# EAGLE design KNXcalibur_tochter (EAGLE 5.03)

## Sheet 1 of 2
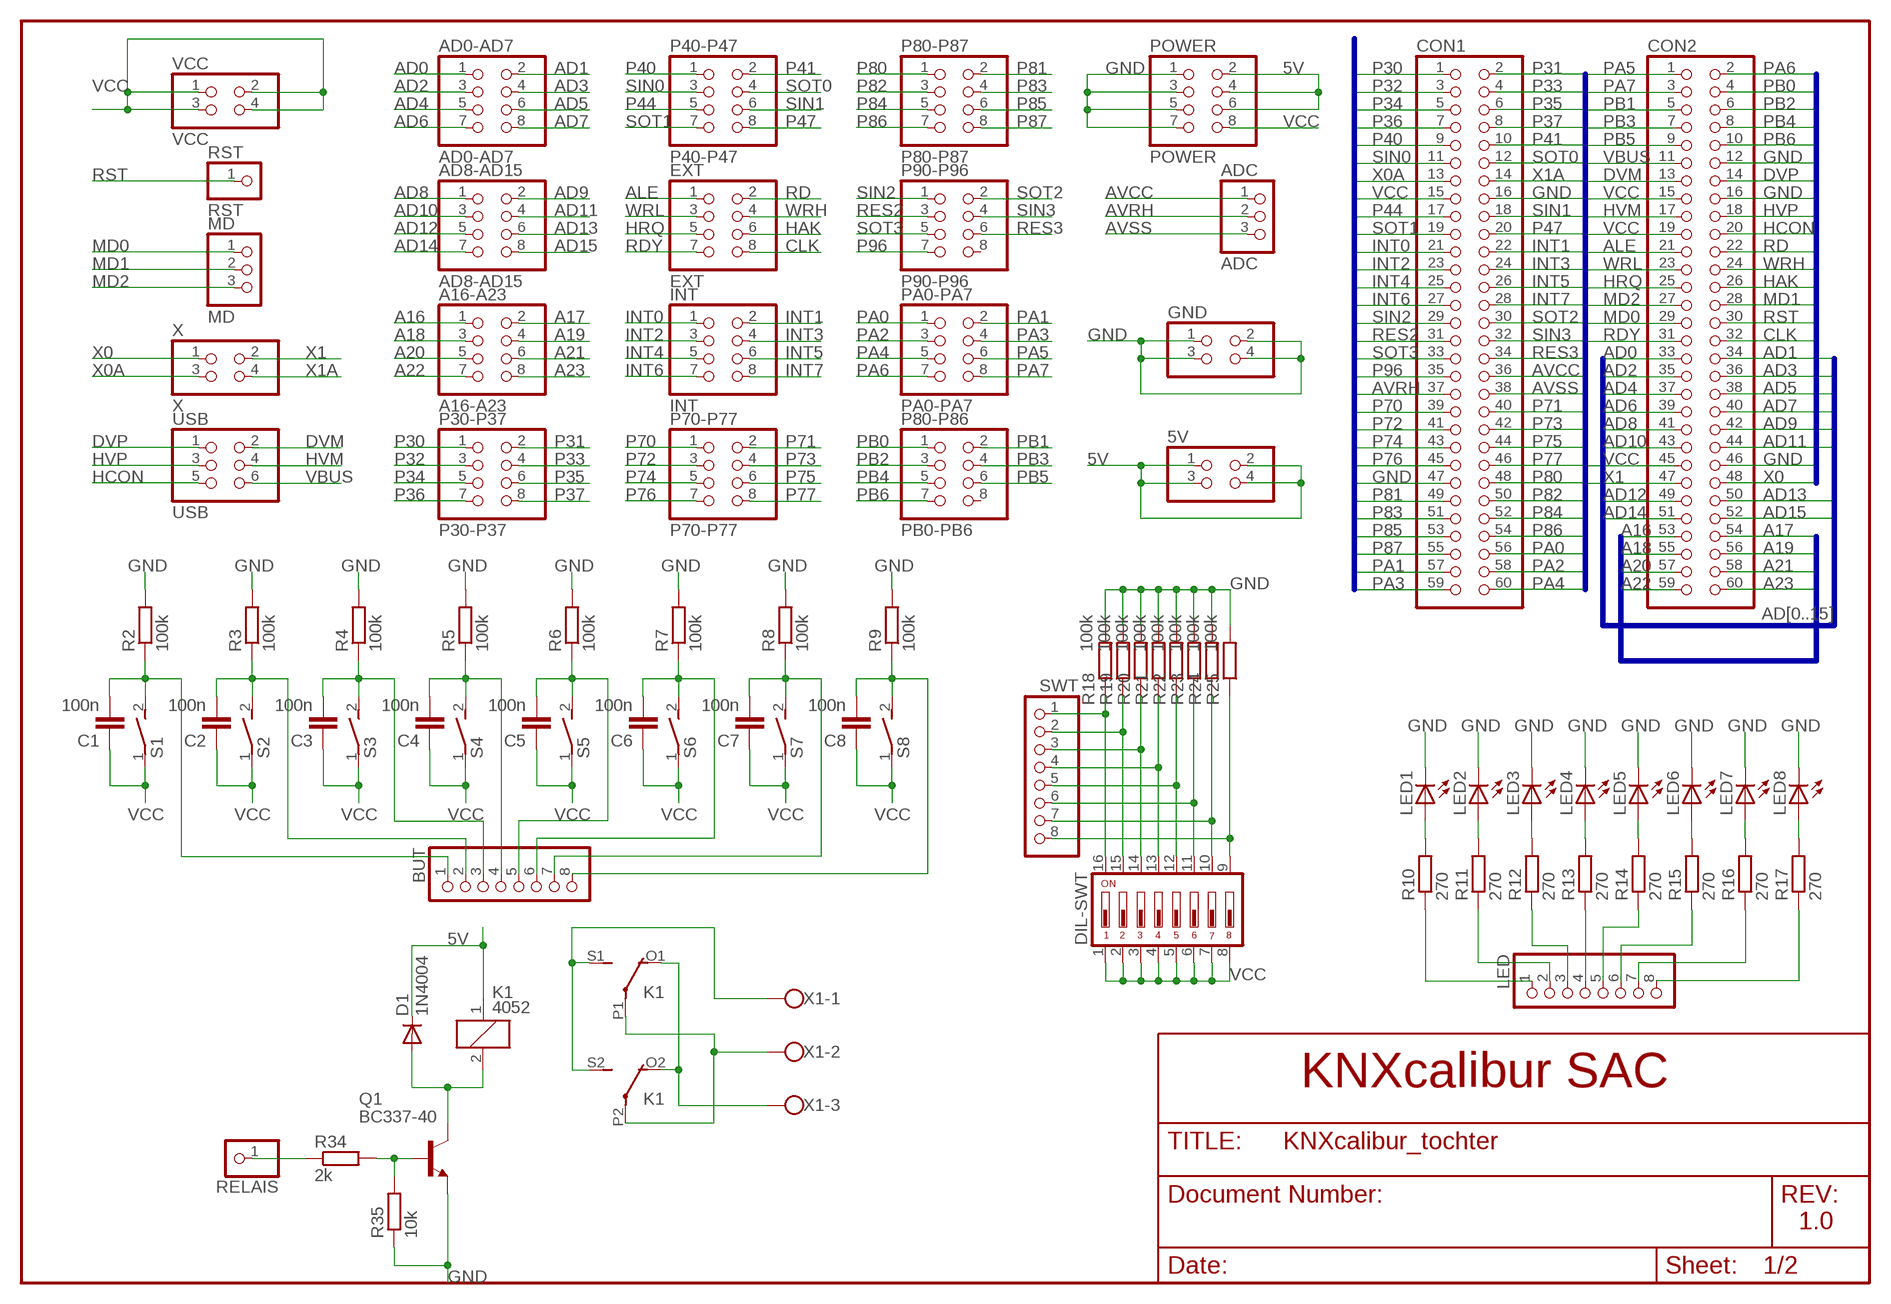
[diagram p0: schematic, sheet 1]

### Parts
5V  PINHD-2X2  [2X02]
A16-A23  A16-A23  PINHD-2X4  [2X04]
AD0-AD7  AD0-AD7  PINHD-2X4  [2X04]
AD8-AD15  AD8-AD15  PINHD-2X4  [2X04]
ADC  ADC  PINHD-1X3  [1X03]
BUT  PINHD-1X8  [1X08]
C1  100n  C-EUC0805  [C0805]
C2  100n  C-EUC0805  [C0805]
C3  100n  C-EUC0805  [C0805]
C4  100n  C-EUC0805  [C0805]
C5  100n  C-EUC0805  [C0805]
C6  100n  C-EUC0805  [C0805]
C7  100n  C-EUC0805  [C0805]
C8  100n  C-EUC0805  [C0805]
CON1  PINHD-2X30  [2X30]
CON2  PINHD-2X30  [2X30]
D1  1N4004  [DO41-10]
DIL-SWT  DIP08YL  [DIP08YL]
EXT  EXT  PINHD-2X4  [2X04]
GND  PINHD-2X2  [2X02]
INT  INT  PINHD-2X4  [2X04]
K1  4052  [F4052]
LED  PINHD-1X8  [1X08]
LED1  LED3MM  [LED3MM]
LED2  LED3MM  [LED3MM]
LED3  LED3MM  [LED3MM]
LED4  LED3MM  [LED3MM]
LED5  LED3MM  [LED3MM]
LED6  LED3MM  [LED3MM]
LED7  LED3MM  [LED3MM]
LED8  LED3MM  [LED3MM]
MD  MD  PINHD-1X3  [1X03]
P30-P37  P30-P37  PINHD-2X4  [2X04]
P40-P47  P40-P47  PINHD-2X4  [2X04]
P70-P77  P70-P77  PINHD-2X4  [2X04]
P80-P86  PB0-PB6  PINHD-2X4  [2X04]
P80-P87  P80-P87  PINHD-2X4  [2X04]
P90-P96  P90-P96  PINHD-2X4  [2X04]
PA0-PA7  PA0-PA7  PINHD-2X4  [2X04]
POWER  POWER  PINHD-2X4  [2X04]
Q1  BC337-40  [TO92]
R2  100k  R-EU_R0805  [R0805]
R3  100k  R-EU_R0805  [R0805]
R4  100k  R-EU_R0805  [R0805]
R5  100k  R-EU_R0805  [R0805]
R6  100k  R-EU_R0805  [R0805]
R7  100k  R-EU_R0805  [R0805]
R8  100k  R-EU_R0805  [R0805]
R9  100k  R-EU_R0805  [R0805]
R10  270  R-EU_R0805  [R0805]
R11  270  R-EU_R0805  [R0805]
R12  270  R-EU_R0805  [R0805]
R13  270  R-EU_R0805  [R0805]
R14  270  R-EU_R0805  [R0805]
R15  270  R-EU_R0805  [R0805]
R16  270  R-EU_R0805  [R0805]
R17  270  R-EU_R0805  [R0805]
R18  100k  R-EU_R0805  [R0805]
R19  100k  R-EU_R0805  [R0805]
R20  100k  R-EU_R0805  [R0805]
R21  100k  R-EU_R0805  [R0805]
R22  100k  R-EU_R0805  [R0805]
R23  100k  R-EU_R0805  [R0805]
R24  100k  R-EU_R0805  [R0805]
R25  100k  R-EU_R0805  [R0805]
R34  2k  R-EU_R0805  [R0805]
R35  10k  R-EU_R0805  [R0805]
RELAIS  PINHD-1X1  [1X01]
RST  RST  PINHD-1X1  [1X01]
S1  DTS-3  [DTS-3]
S2  DTS-3  [DTS-3]
S3  DTS-3  [DTS-3]
S4  DTS-3  [DTS-3]
S5  DTS-3  [DTS-3]
S6  DTS-3  [DTS-3]
S7  DTS-3  [DTS-3]
S8  DTS-3  [DTS-3]
SWT  PINHD-1X8  [1X08]
USB  USB  PINHD-2X3  [2X03]
VCC  VCC  PINHD-2X2  [2X02]
X  X  PINHD-2X2  [2X02]
X1  W237-103  [W237-103]

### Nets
5V: 5V.1 5V.2 5V.3 5V.4 D1.C K1.1 POWER.2 POWER.4 POWER.6 ; also sheet 2
A16: A16-A23.1 CON2.53
A17: A16-A23.2 CON2.54
A18: A16-A23.3 CON2.55
A19: A16-A23.4 CON2.56
A20: A16-A23.5 CON2.57
A21: A16-A23.6 CON2.58
A22: A16-A23.7 CON2.59
A23: A16-A23.8 CON2.60
AD0: AD0-AD7.1 CON2.33
AD1: AD0-AD7.2 CON2.34
AD2: AD0-AD7.3 CON2.35
AD3: AD0-AD7.4 CON2.36
AD4: AD0-AD7.5 CON2.37
AD5: AD0-AD7.6 CON2.38
AD6: AD0-AD7.7 CON2.39
AD7: AD0-AD7.8 CON2.40
AD8: AD8-AD15.1 CON2.41
AD9: AD8-AD15.2 CON2.42
AD10: AD8-AD15.3 CON2.43
AD11: AD8-AD15.4 CON2.44
AD12: AD8-AD15.5 CON2.49
AD13: AD8-AD15.6 CON2.50
AD14: AD8-AD15.7 CON2.51
AD15: AD8-AD15.8 CON2.52
ALE: CON2.21 EXT.1
AVCC: ADC.1 CON1.36
AVRH: ADC.2 CON1.37
AVSS: ADC.3 CON1.38
CLK: CON2.32 EXT.8
DVM: CON2.13 USB.2
DVP: CON2.14 USB.1
GND: CON1.16 CON1.47 CON2.12 CON2.16 CON2.46 GND.1 GND.2 GND.3 GND.4 LED1.K(C) LED2.K(C) LED3.K(C) LED4.K(C) LED5.K(C) LED6.K(C) LED7.K(C) LED8.K(C) POWER.1 POWER.3 POWER.5 POWER.7 Q1.1(E) R2.2 R3.2 R4.2 R5.2 R6.2 R7.2 R8.2 R9.2 R18.2 R19.2 R20.2 R21.2 R22.2 R23.2 R24.2 R25.2 R35.1 ; also sheet 2
HAK: CON2.26 EXT.6
HCON: CON2.20 USB.5
HRQ: CON2.25 EXT.5
HVM: CON2.17 USB.4
HVP: CON2.18 USB.3
INT0: CON1.21 INT.1
INT1: CON1.22 INT.2
INT2: CON1.23 INT.3 ; also sheet 2
INT3: CON1.24 INT.4 ; also sheet 2
INT4: CON1.25 INT.5 ; also sheet 2
INT5: CON1.26 INT.6 ; also sheet 2
INT6: CON1.27 INT.7 ; also sheet 2
INT7: CON1.28 INT.8
MD0: CON2.29 MD.1
MD1: CON2.28 MD.2
MD2: CON2.27 MD.3
N$2: DIL-SWT.16 R18.1 SWT.1
N$3: DIL-SWT.15 R19.1 SWT.2
N$4: DIL-SWT.14 R20.1 SWT.3
N$5: DIL-SWT.13 R21.1 SWT.4
N$6: DIL-SWT.12 R22.1 SWT.5
N$7: DIL-SWT.11 R23.1 SWT.6
N$8: DIL-SWT.10 R24.1 SWT.7
N$9: DIL-SWT.9 R25.1 SWT.8
N$15: BUT.1 C1.2 R2.1 S1.2
N$16: BUT.2 C2.2 R3.1 S2.2
N$17: BUT.3 C3.2 R4.1 S3.2
N$18: BUT.4 C4.2 R5.1 S4.2
N$19: BUT.5 C5.2 R6.1 S5.2
N$20: BUT.6 C6.2 R7.1 S6.2
N$21: BUT.7 C7.2 R8.1 S7.2
N$22: BUT.8 C8.2 R9.1 S8.2
N$23: LED1.A R10.2
N$24: LED.1 R10.1
N$25: LED2.A R11.2
N$26: LED.2 R11.1
N$27: LED3.A R12.2
N$28: LED.3 R12.1
N$29: LED4.A R13.2
N$30: LED.4 R13.1
N$31: LED5.A R14.2
N$32: LED.5 R14.1
N$33: LED6.A R15.2
N$34: LED.6 R15.1
N$35: LED7.A R16.2
N$36: LED.7 R16.1
N$37: LED8.A R17.2
N$38: LED.8 R17.1
N$54: K1.P1(2:P) K1.P2(3:P) X1.2
N$55: R34.1 RELAIS.1
N$57: K1.S1(2:S) K1.S2(3:S) X1.1
N$58: K1.O1(2:O) K1.O2(3:O) X1.3
N$59: Q1.2(B) R34.2 R35.2
N$61: D1.A K1.2 Q1.3(C)
P30: CON1.1 P30-P37.1 ; also sheet 2
P31: CON1.2 P30-P37.2 ; also sheet 2
P32: CON1.3 P30-P37.3 ; also sheet 2
P33: CON1.4 P30-P37.4 ; also sheet 2
P34: CON1.5 P30-P37.5 ; also sheet 2
P35: CON1.6 P30-P37.6
P36: CON1.7 P30-P37.7
P37: CON1.8 P30-P37.8
P40: CON1.9 P40-P47.1
P41: CON1.10 P40-P47.2
P44: CON1.17 P40-P47.5
P47: CON1.20 P40-P47.8
P70: CON1.39 P70-P77.1
P71: CON1.40 P70-P77.2
P72: CON1.41 P70-P77.3
P73: CON1.42 P70-P77.4
P74: CON1.43 P70-P77.5
P75: CON1.44 P70-P77.6
P76: CON1.45 P70-P77.7
P77: CON1.46 P70-P77.8
P80: CON1.48 P80-P87.1
P81: CON1.49 P80-P87.2
P82: CON1.50 P80-P87.3
P83: CON1.51 P80-P87.4
P84: CON1.52 P80-P87.5
P85: CON1.53 P80-P87.6
P86: CON1.54 P80-P87.7
P87: CON1.55 P80-P87.8
P96: CON1.35 P90-P96.7
PA0: CON1.56 PA0-PA7.1
PA1: CON1.57 PA0-PA7.2
PA2: CON1.58 PA0-PA7.3
PA3: CON1.59 PA0-PA7.4
PA4: CON1.60 PA0-PA7.5
PA5: CON2.1 PA0-PA7.6
PA6: CON2.2 PA0-PA7.7
PA7: CON2.3 PA0-PA7.8
PB0: CON2.4 P80-P86.1
PB1: CON2.5 P80-P86.2
PB2: CON2.6 P80-P86.3
PB3: CON2.7 P80-P86.4
PB4: CON2.8 P80-P86.5
PB5: CON2.9 P80-P86.6
PB6: CON2.10 P80-P86.7
RD: CON2.22 EXT.2
RDY: CON2.31 EXT.7
RES2: CON1.31 P90-P96.3
RES3: CON1.34 P90-P96.6
RST: CON2.30 RST.1
SIN0: CON1.11 P40-P47.3
SIN1: CON1.18 P40-P47.6
SIN2: CON1.29 P90-P96.1
SIN3: CON1.32 P90-P96.4
SOT0: CON1.12 P40-P47.4
SOT1: CON1.19 P40-P47.7
SOT2: CON1.30 P90-P96.2
SOT3: CON1.33 P90-P96.5
VBUS: CON2.11 USB.6
VCC: C1.1 C2.1 C3.1 C4.1 C5.1 C6.1 C7.1 C8.1 CON1.15 CON2.15 CON2.19 CON2.45 DIL-SWT.1 DIL-SWT.2 DIL-SWT.3 DIL-SWT.4 DIL-SWT.5 DIL-SWT.6 DIL-SWT.7 DIL-SWT.8 POWER.8 S1.1 S2.1 S3.1 S4.1 S5.1 S6.1 S7.1 S8.1 VCC.1 VCC.2 VCC.3 VCC.4 ; also sheet 2
WRH: CON2.24 EXT.4
WRL: CON2.23 EXT.3
X0: CON2.48 X.1
X0A: CON1.13 X.3
X1: CON2.47 X.2
X1A: CON1.14 X.4
Unconnected: P80-P86.8 P90-P96.8

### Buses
AD[0..15]
A[0..23]
P[30..37],P40,P41,P44,P47,SIN[0..3],SOT[0..3],INT[0..7],X0A,X1A,VCC,GND,RES2,RES3,P96,AVCC,AVRH,AVSS,P[70..77],P[80..87],PA[0..7],PB[0..6],VBUS,DVM,DVP,HVM,HVP,HCON,ALE,RD,WRL,WRH,HRQ,HAK,RDY,CLK,MD[0..2],RST,X[0..1]

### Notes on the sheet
- KNXcalibur SAC
- 1.0

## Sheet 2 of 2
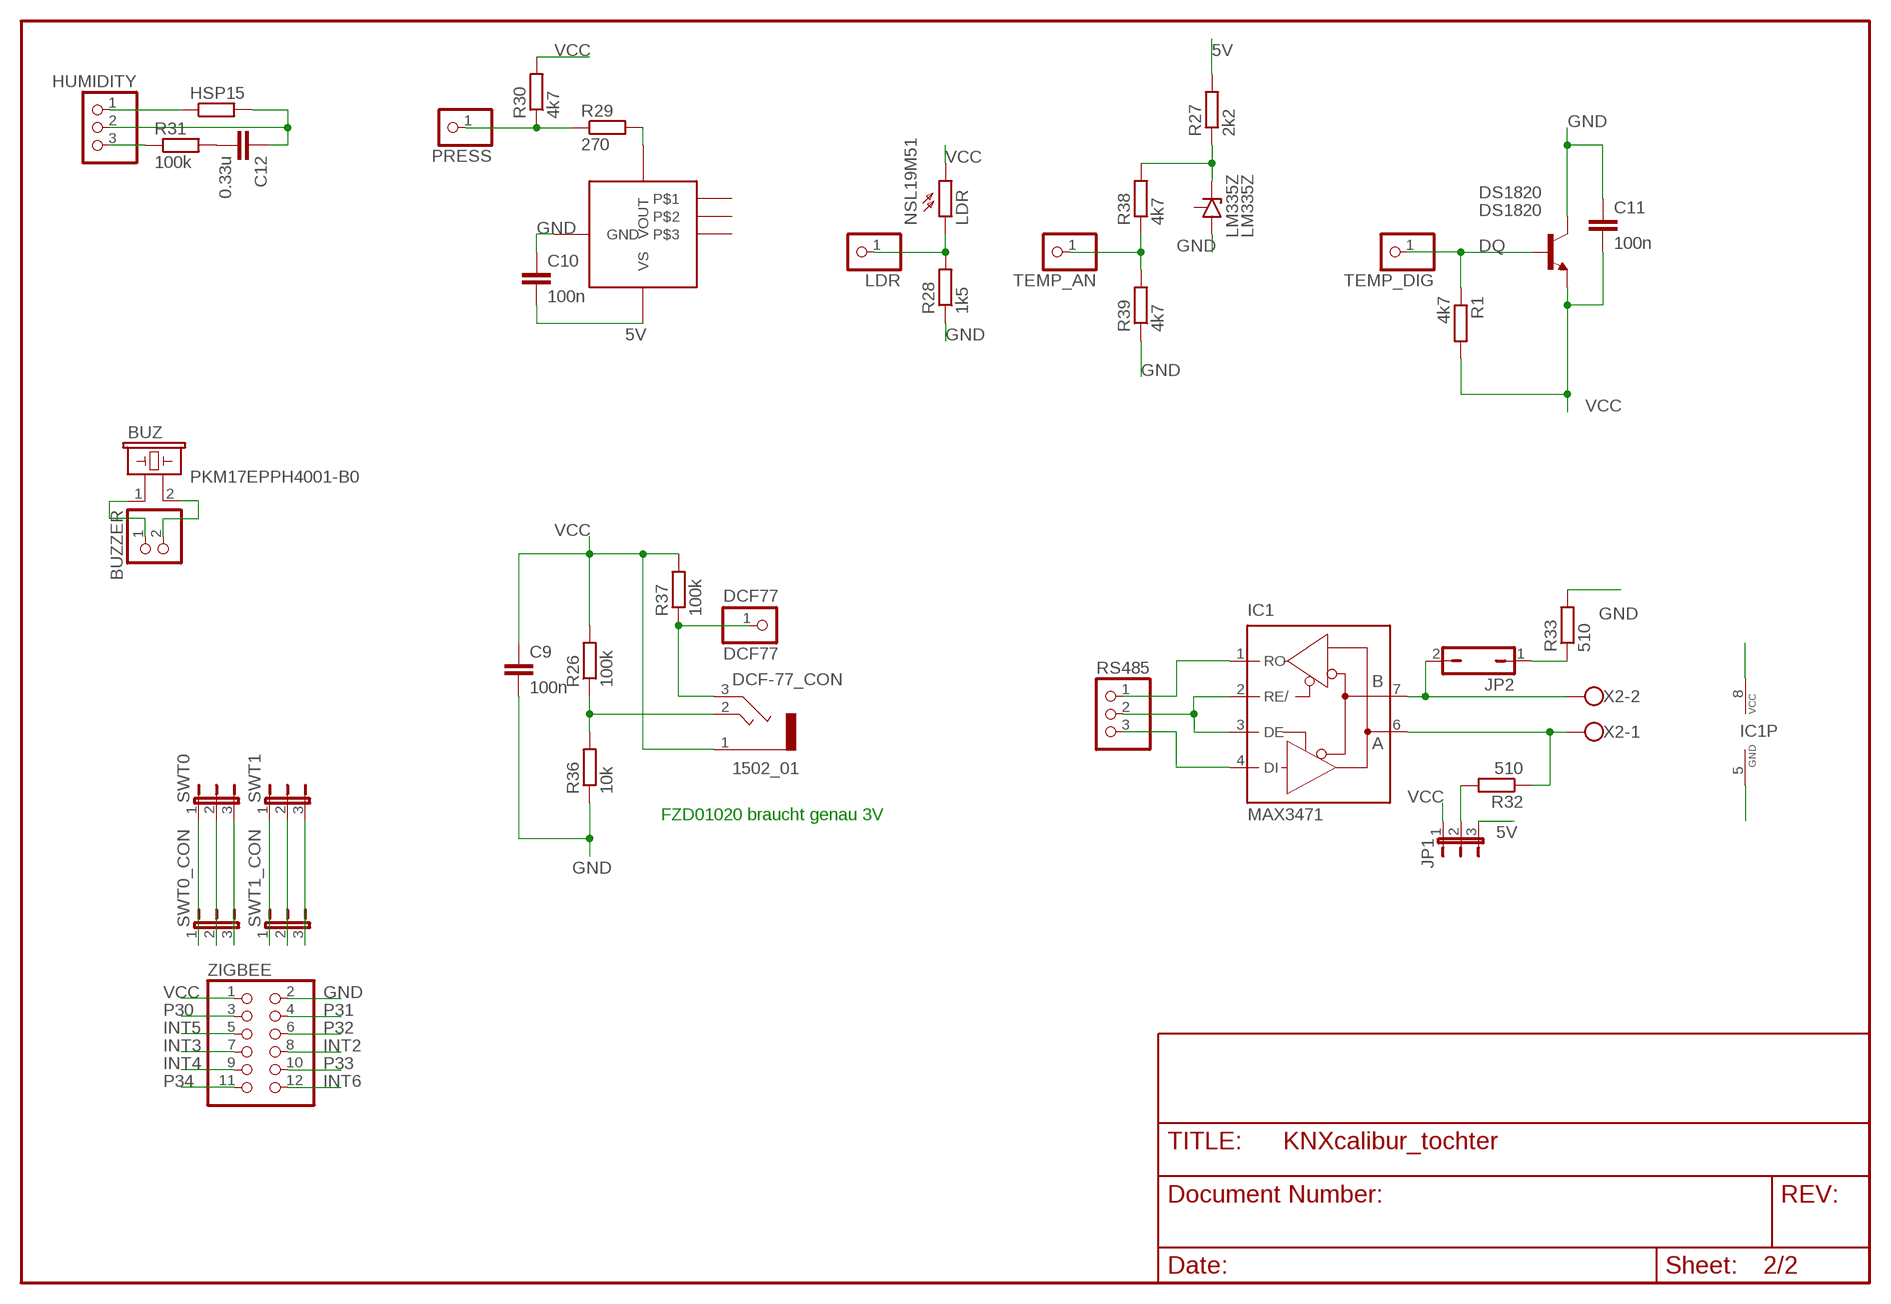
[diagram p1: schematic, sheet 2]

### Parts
BUZ  PKM17EPPH4001-B0  F/EE17P  [F/EE17P]
BUZZER  PINHD-1X2  [1X02]
C9  100n  C-EUC0805  [C0805]
C10  100n  C-EUC0805  [C0805]
C11  100n  C-EUC0805  [C0805]
C12  0.33u  C-EUC0805  [C0805]
DCF77  DCF77  PINHD-1X1  [1X01]
DCF-77_CON  1502_01  [1502_01]
DS1820  DS1820  BC546A  [TO92-EBC]
HSP15  HS15P  [HS15P]
HUMIDITY  PINHD-1X3  [1X03]
IC1  MAX3471  [UMAX8]
JP1  JP2E  [JP2]
JP2  JP1Q  [JP1]
LDR  PINHD-1X1  [1X01]
LM335Z  LM335Z  [WH_MISC_TO92]
MPX4250  MPX4250A  [MPX4250A_UNIBODY]
NSL19M51  LDR  [WH_RCL_LDR00]
PRESS  PINHD-1X1  [1X01]
R1  4k7  R-EU_M0805  [M0805]
R26  100k  R-EU_R0805  [R0805]
R27  2k2  R-EU_R0805  [R0805]
R28  1k5  R-EU_R0805  [R0805]
R29  270  R-EU_R0805  [R0805]
R30  4k7  R-EU_R0805  [R0805]
R31  100k  R-EU_R0805  [R0805]
R32  510  R-EU_R0805  [R0805]
R33  510  R-EU_R0805  [R0805]
R36  10k  R-EU_R0805  [R0805]
R37  100k  R-EU_R0805  [R0805]
R38  4k7  R-EU_R0805  [R0805]
R39  4k7  R-EU_R0805  [R0805]
RS485  PINHD-1X3  [1X03]
SWT0  JP2E  [JP2]
SWT0_CON  JP2E  [JP2]
SWT1  JP2E  [JP2]
SWT1_CON  JP2E  [JP2]
TEMP_AN  PINHD-1X1  [1X01]
TEMP_DIG  PINHD-1X1  [1X01]
X2  W237-102  [W237-102]
ZIGBEE  PINHD-2X6  [2X06]

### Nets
5V: C10.2 JP1.3 MPX4250.P$3(VS) R27.2 ; also sheet 1
ADC: C12.1 HSP15.2 HUMIDITY.2
DI: IC1.4(DI) RS485.3
DQ: DS1820.B R1.1 TEMP_DIG.1
GND: C9.2 C10.1 C11.1 DS1820.C IC1.5(GND) LM335Z.1(A) MPX4250.P$2(GND) R28.1 R33.2 R36.1 R39.1 ZIGBEE.2 ; also sheet 1
GND_AC: HUMIDITY.3 R31.1
INT2: ZIGBEE.8 ; also sheet 1
INT3: ZIGBEE.7 ; also sheet 1
INT4: ZIGBEE.9 ; also sheet 1
INT5: ZIGBEE.5 ; also sheet 1
INT6: ZIGBEE.12 ; also sheet 1
N$1: SWT1.1 SWT1_CON.1
N$10: SWT1.2 SWT1_CON.2
N$11: SWT1.3 SWT1_CON.3
N$12: SWT0.1 SWT0_CON.1
N$13: SWT0.2 SWT0_CON.2
N$14: SWT0.3 SWT0_CON.3
N$39: DCF77.1 DCF-77_CON.3 R37.1
N$40: LM335Z.2(C) R27.1 R38.2
N$41: LDR.1 NSL19M51.1 R28.2
N$42: MPX4250.P$1(VOUT) R29.2
N$43: PRESS.1 R29.1 R30.1
N$44: BUZ.1 BUZZER.1
N$45: BUZ.2 BUZZER.2
N$46: C12.2 R31.2
N$47: DCF-77_CON.2 R26.1 R36.2
N$48: R38.1 R39.2 TEMP_AN.1
N$50: JP1.2 R32.2
N$51: JP2.1 R33.1
N$52: IC1.7(B) JP2.2 X2.2
N$53: IC1.6(A) R32.1 X2.1
P30: ZIGBEE.3 ; also sheet 1
P31: ZIGBEE.4 ; also sheet 1
P32: ZIGBEE.6 ; also sheet 1
P33: ZIGBEE.10 ; also sheet 1
P34: ZIGBEE.11 ; also sheet 1
RE/_DE: IC1.2(RE/) IC1.3(DE) RS485.2
RO: IC1.1(RO) RS485.1
VCC: C9.1 C11.2 DCF-77_CON.1 DS1820.E IC1.8(VCC) JP1.1 NSL19M51.2 R1.2 R26.2 R30.2 R37.2 ZIGBEE.1 ; also sheet 1
VCC_AC: HSP15.1 HUMIDITY.1
Unconnected: LM335Z.3(ADJ) MPX4250.P$4 MPX4250.P$5 MPX4250.P$6

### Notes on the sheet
- FZD01020 braucht genau 3V

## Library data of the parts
5V GND VCC X = pinhead:PINHD-2X2: PIN HEADER
A16-A23 AD0-AD7 AD8-AD15 EXT INT P30-P37 P40-P47 P70-P77 P80-P86 P80-P87 P90-P96 PA0-PA7 POWER = pinhead:PINHD-2X4: PIN HEADER
ADC HUMIDITY MD RS485 = pinhead:PINHD-1X3: PIN HEADER
BUT LED SWT = pinhead:PINHD-1X8: PIN HEADER
BUZ = buzzer:F/EE17P: BUZZER
BUZZER = pinhead:PINHD-1X2: PIN HEADER
C1-C12 = rcl:C-EU: CAPACITOR, European symbol
CON1 CON2 = pinhead:PINHD-2X30: PIN HEADER
D1 = diode:1N4004: DIODE
DCF77 LDR PRESS RELAIS RST TEMP_AN TEMP_DIG = pinhead:PINHD-1X1: PIN HEADER
DCF-77_CON = con-lumberg:1502_01: Jack connectors according to JISC 6560, 3.5 mm Klinkensteckverbinder nach JISC 6560, 3,5 mm Source: http://www.lumberg.com/Produkte/PDFs/1502_01.pdf
DIL-SWT = switch-dil:DIP08YL: DIL/CODE SWITCH
DS1820 = transistor-npn:BC546*: NPN Transistor
HSP15 = eibsec:HS15P: RESISTOR, European symbol
IC1 = eibsec:MAX3471: RS485 TRANSEIVER
JP1 SWT0 SWT0_CON SWT1 SWT1_CON = jumper:JP2E: JUMPER
JP2 = jumper:JP1Q: JUMPER
K1 = relay:4052: RELAY 2 x switch, Finder
LED1-LED8 = led:LED: LED
LM335Z = eibsec:LM335
MPX4250 = eibsec:MPX4250A
NSL19M51 = eibsec:LDR
Q1 = transistor-npn:BC337*: NPN Transistor
R1-R39 = rcl:R-EU_: RESISTOR, European symbol
S1-S8 = eibsec:DTS-3: DIL/CODE SWITCH
USB = pinhead:PINHD-2X3: PIN HEADER
X1 = con-wago-500:W237-103: WAGO SCREW CLAMP
X2 = con-wago-500:W237-102: WAGO SCREW CLAMP
ZIGBEE = pinhead:PINHD-2X6: PIN HEADER

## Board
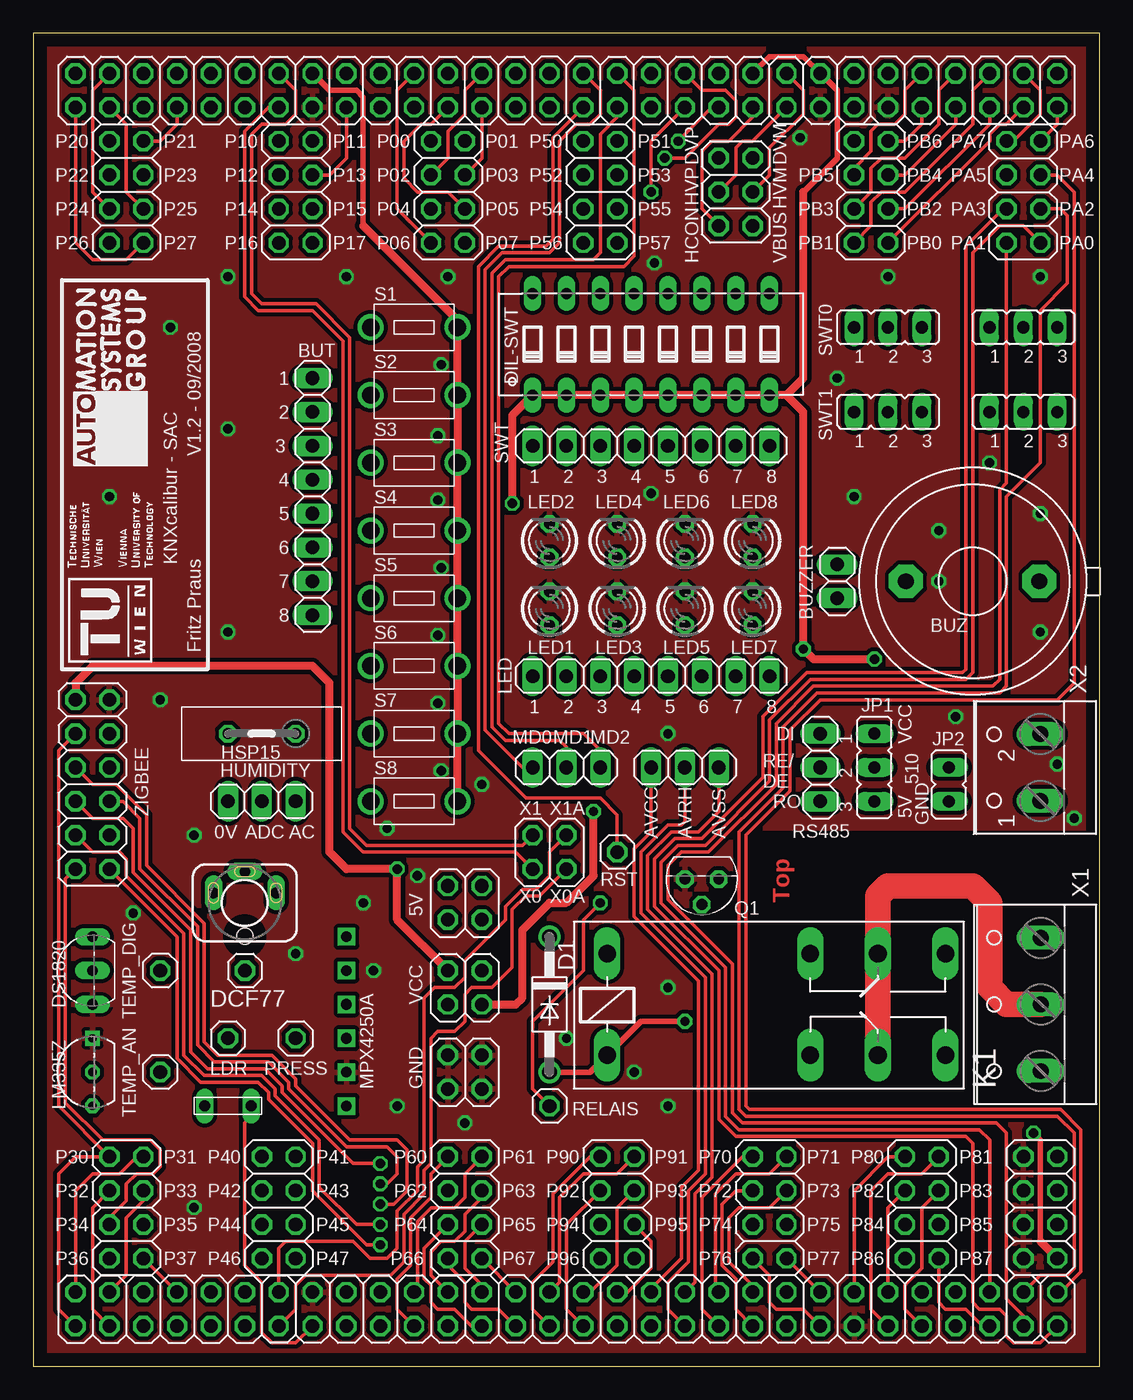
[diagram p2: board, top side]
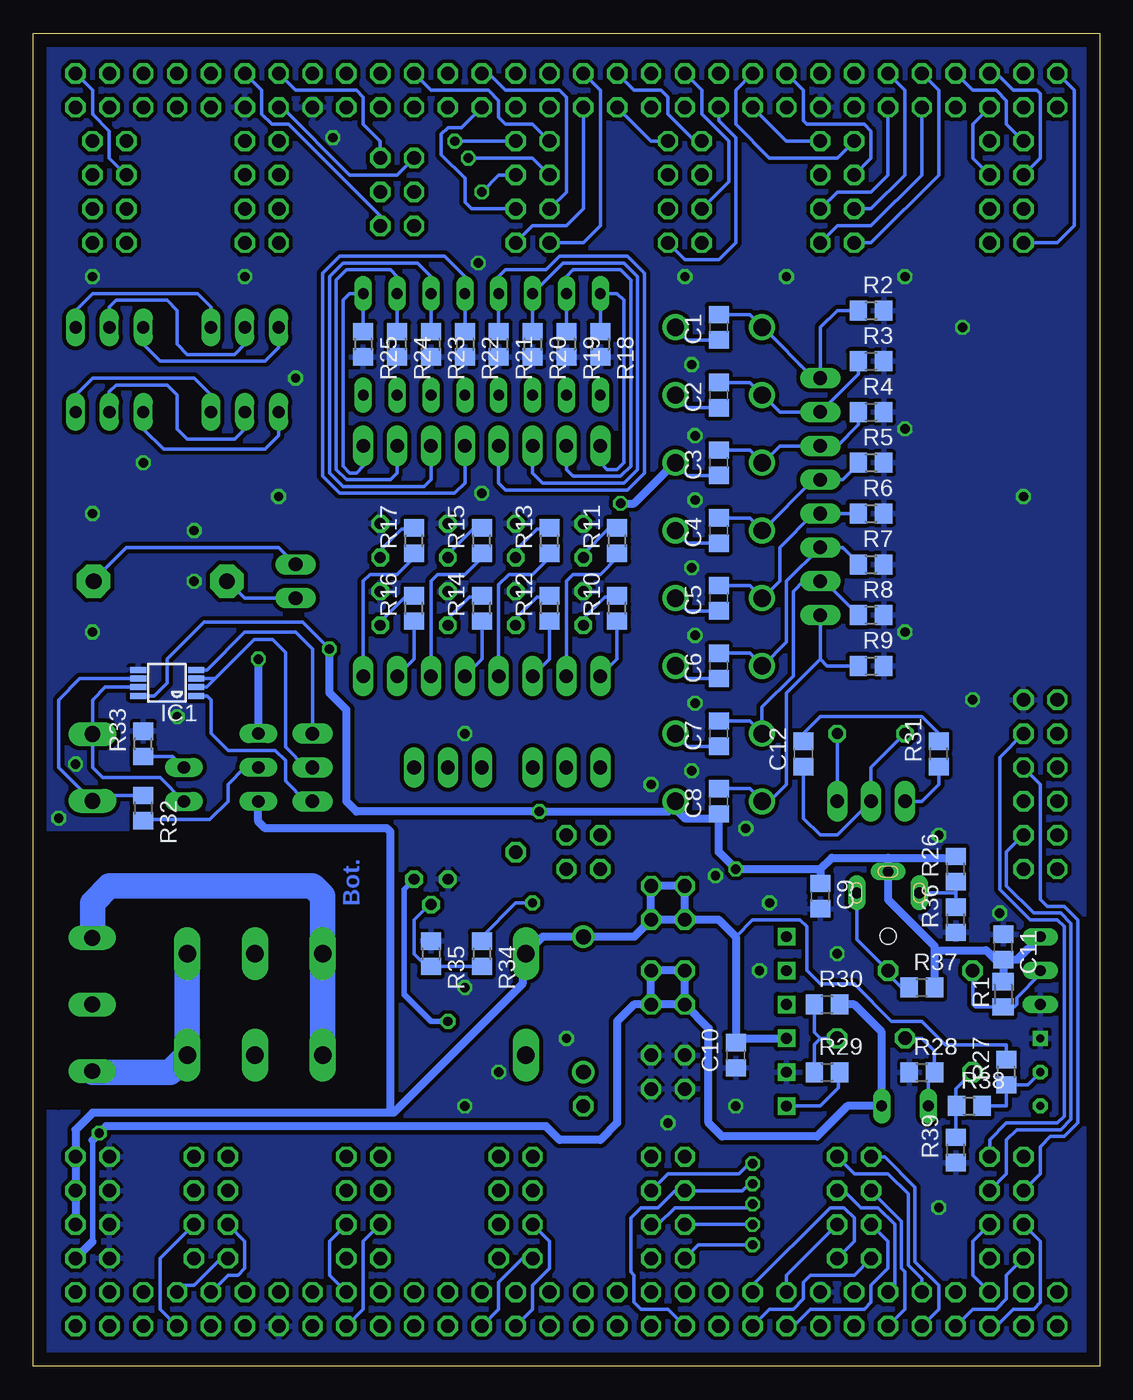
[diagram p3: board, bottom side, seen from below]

Size 80 x 100 mm. Coordinates in mm from the lower left corner, seen from the top.
Outline: 0,0 80,0 80,100 0,100 0,0
Copper layers (1*16): Top 0.035mm / dielectric 1.5mm / Bottom 0.035mm
Design rules "olimex_10mils *": minimum track width 10mil, minimum drill 24mil, track to track 10mil, track to pad 10mil, pad to pad 10mil, via to via 10mil, smd to smd 10mil, copper to edge 40mil, drill to drill 10mil, minimum pad ring 10mil, minimum via ring 8mil, stop-mask expansion 0mil, vias tented up to drill 0mil, thermal gap 10mil
tRestrict: area 54,19.5 to 55.2,39.8; area 55.2,38.6 to 79.4,39.8; area 55.2,19.5 to 79.4,20.8
bRestrict: area 54,20.8 to 55.2,38.6; area 54,38.6 to 78.1,39.8; area 78.1,19.5 to 79.4,39.8; area 54,19.5 to 79.4,20.8

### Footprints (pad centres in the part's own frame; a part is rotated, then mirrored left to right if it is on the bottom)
2X02 = drill 1.016 octagon: 1 -1.27,-1.27; 2 -1.27,1.27; 3 1.27,-1.27; 4 1.27,1.27
2X04 = drill 1.016 octagon: 1 -3.81,-1.27; 2 -3.81,1.27; 3 -1.27,-1.27; 4 -1.27,1.27; 5 1.27,-1.27; 6 1.27,1.27; 7 3.81,-1.27; 8 3.81,1.27
1X03 = drill 1.016 long: 1 -2.54,0; 2 0,0; 3 2.54,0
1X08 = drill 1.016 long: 1 -8.89,0; 2 -6.35,0; 3 -3.81,0; 4 -1.27,0; 5 1.27,0; 6 3.81,0; 7 6.35,0; 8 8.89,0
F/EE17P = drill 1.194 pad 2.54 octagon: 1 -5.004,0; 2 5.004,0
1X02 = drill 1.016 long: 1 -1.27,0; 2 1.27,0
C0805 = smd 1.3 x 1.5: 1 -0.95,0; 2 0.95,0
2X30 = drill 1.016 octagon: 1 -38.1,-1.27; 2 -38.1,1.27; 3 -35.56,-1.27; 4 -35.56,1.27; 5 -33.02,-1.27; 6 -33.02,1.27; 7 -30.48,-1.27; 8 -30.48,1.27; 9 -27.94,-1.27; 10 -27.94,1.27; 11 -25.4,-1.27; 12 -25.4,1.27; 13 -22.86,-1.27; 14 -22.86,1.27; 15 -20.32,-1.27; 16 -20.32,1.27; 17 -17.78,-1.27; 18 -17.78,1.27; 19 -15.24,-1.27; 20 -15.24,1.27; 21 -12.7,-1.27; 22 -12.7,1.27; 23 -10.16,-1.27; 24 -10.16,1.27; 25 -7.62,-1.27; 26 -7.62,1.27; 27 -5.08,-1.27; 28 -5.08,1.27; 29 -2.54,-1.27; 30 -2.54,1.27; 31 0,-1.27; 32 0,1.27; 33 2.54,-1.27; 34 2.54,1.27; 35 5.08,-1.27; 36 5.08,1.27; 37 7.62,-1.27; 38 7.62,1.27; 39 10.16,-1.27; 40 10.16,1.27; 41 12.7,-1.27; 42 12.7,1.27; 43 15.24,-1.27; 44 15.24,1.27; 45 17.78,-1.27; 46 17.78,1.27; 47 20.32,-1.27; 48 20.32,1.27; 49 22.86,-1.27; 50 22.86,1.27; 51 25.4,-1.27; 52 25.4,1.27; 53 27.94,-1.27; 54 27.94,1.27; 55 30.48,-1.27; 56 30.48,1.27; 57 33.02,-1.27; 58 33.02,1.27; 59 35.56,-1.27; 60 35.56,1.27
DO41-10 = drill 1.118 round: A 5.08,0; C -5.08,0
1X01 = drill 1.016 octagon: 1 0,0
1502_01 = drill 0.8 pad 1.2 long: 1 0,2.35; 2 -2.35,0.75; 3 2.35,0.75 | hole 1.2: 0,-2.5
DIP08YL = drill 0.813 long: 1 -8.89,-3.81; 2 -6.35,-3.81; 3 -3.81,-3.81; 4 -1.27,-3.81; 5 1.27,-3.81; 6 3.81,-3.81; 7 6.35,-3.81; 8 8.89,-3.81; 9 8.89,3.81; 10 6.35,3.81; 11 3.81,3.81; 12 1.27,3.81; 13 -1.27,3.81; 14 -3.81,3.81; 15 -6.35,3.81; 16 -8.89,3.81
TO92-EBC = drill 0.813 long: B 0,-1.27; C -2.54,-1.27; E 2.54,-1.27
HS15P = drill 0.813 octagon: 1 -2.54,0; 2 2.54,0
UMAX8 = smd 0.45 x 1.2: 1 -0.975,-2.175; 2 -0.325,-2.175; 3 0.325,-2.175; 4 0.975,-2.175; 5 0.975,2.175; 6 0.325,2.175; 7 -0.325,2.175; 8 -0.975,2.175
JP2 = drill 0.914 long: 1 -2.54,0; 2 0,0; 3 2.54,0
JP1 = drill 0.914 long: 1 0,-1.27; 2 0,1.27
F4052 = drill 1.321 long: 1 -3.81,3.81; 2 -3.81,-3.81; O1 11.43,-3.81; O2 11.43,3.81; P1 16.51,-3.81; P2 16.51,3.81; S1 21.59,-3.81; S2 21.59,3.81
LED3MM = drill 0.813 octagon: A -1.27,0; K 1.27,0
WH_MISC_TO92 = drill 0.61 pad 0.813 square: 1 2.54,0 | drill 0.61 pad 0.813 octagon: 2 0,0; 3 -2.54,0
MPX4250A_UNIBODY = drill 0.8 square: P$1 -7.62,0; P$2 -5.08,0; P$3 -2.54,0; P$4 0,0; P$5 2.54,0; P$6 5.08,0
WH_RCL_LDR00 = drill 0.813 long: 1 -1.75,0; 2 1.75,0
TO92 = drill 0.813 octagon: 1 1.27,0; 2 0,1.905; 3 -1.27,0
M0805 = smd 1.3 x 1.6: 1 -0.95,0; 2 0.95,0
R0805 = smd 1.3 x 1.5: 1 -0.95,0; 2 0.95,0
DTS-3 = drill 1.3 round: 1 3.25,0; 2 -3.25,0
2X03 = drill 1.016 octagon: 1 -2.54,-1.27; 2 -2.54,1.27; 3 0,-1.27; 4 0,1.27; 5 2.54,-1.27; 6 2.54,1.27
W237-103 = drill 1.194 long: 1 -5,-1.29; 2 0,-1.29; 3 5,-1.29
W237-102 = drill 1.194 long: 1 -2.5,-1.27; 2 2.5,-1.27
2X06 = drill 1.016 octagon: 1 -6.35,-1.27; 2 -6.35,1.27; 3 -3.81,-1.27; 4 -3.81,1.27; 5 -1.27,-1.27; 6 -1.27,1.27; 7 1.27,-1.27; 8 1.27,1.27; 9 3.81,-1.27; 10 3.81,1.27; 11 6.35,-1.27; 12 6.35,1.27

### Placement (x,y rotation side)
5V  32.38,34.76 0 top
A16-A23  6.98,88.1 270 top
AD0-AD7  31.11,88.1 270 top
AD8-AD15  19.68,88.1 270 top
ADC  48.89,44.92 0 top
BUT  20.95,65.24 270 top
BUZ  70.48,58.89 0 top
BUZZER  60.32,58.89 90 top
C1  28.57,77.94 90 bottom
C2  28.57,72.86 90 bottom
C3  28.57,67.78 90 bottom
C4  28.57,62.7 90 bottom
C5  28.57,57.62 90 bottom
C6  28.57,52.54 90 bottom
C7  28.57,47.46 90 bottom
C8  28.57,42.38 90 bottom
C9  20.95,35.27 270 bottom
C10  27.3,23.33 90 bottom
C11  7.23,31.46 270 bottom
C12  22.22,45.94 90 bottom
CON1  41.27,4.28 0 top
CON2  38.73,95.72 180 top
D1  38.73,27.14 270 top
DCF77  15.87,29.68 0 top
DCF-77_CON  15.87,34.76 0 top
DIL-SWT  46.35,76.67 0 top
DS1820  3.17,29.68 90 top
EXT  42.54,88.1 270 top
GND  32.38,22.06 0 top
HSP15  17.14,47.46 180 top
HUMIDITY  17.14,42.38 180 top
IC1  69.97,51.27 90 bottom
INT  32.38,11.9 270 top
JP1  63.11,44.92 270 top
JP2  68.7,43.65 180 top
K1  46.86,27.14 0 top
LDR  14.6,24.6 0 top
LED  46.35,51.78 0 top
LED1  38.73,56.86 90 top
LED2  38.73,61.94 90 top
LED3  43.81,56.86 90 top
LED4  43.81,61.94 90 top
LED5  48.89,56.86 90 top
LED6  48.89,61.94 90 top
LED7  53.97,56.86 90 top
LED8  53.97,61.94 90 top
LM335Z  4.44,22.06 90 top
MD  40,44.92 0 top
MPX4250  23.49,27.14 90 top
NSL19M51  14.6,19.52 0 top
P30-P37  6.98,11.9 270 top
P40-P47  18.41,11.9 270 top
P70-P77  55.24,11.9 270 top
P80-P86  62.86,88.1 90 top
P80-P87  66.67,11.9 270 top
P90-P96  43.81,11.9 270 top
PA0-PA7  74.29,88.1 90 top
POWER  75.56,11.9 270 top
PRESS  19.68,24.6 90 top
Q1  50.16,36.54 180 top
R1  7.23,27.9 90 bottom
R2  17.14,79.21 0 bottom
R3  17.14,75.4 0 bottom
R4  17.14,71.59 0 bottom
R5  17.14,67.78 0 bottom
R6  17.14,63.97 0 bottom
R7  17.14,60.16 0 bottom
R8  17.14,56.35 0 bottom
R9  17.14,52.54 0 bottom
R10  36.19,56.86 90 bottom
R11  36.19,61.94 90 bottom
R12  41.27,56.86 90 bottom
R13  41.27,61.94 90 bottom
R14  46.35,56.86 90 bottom
R15  46.35,61.94 90 bottom
R16  51.43,56.86 90 bottom
R17  51.43,61.94 90 bottom
R18  37.46,76.67 270 bottom
R19  40,76.67 270 bottom
R20  42.54,76.67 270 bottom
R21  45.08,76.67 270 bottom
R22  47.62,76.67 270 bottom
R23  50.16,76.67 270 bottom
R24  52.7,76.67 270 bottom
R25  55.24,76.67 270 bottom
R26  10.79,37.3 90 bottom
R27  6.98,22.06 90 bottom
R28  13.33,22.06 0 bottom
R29  20.44,22.06 0 bottom
R30  20.44,27.14 0 bottom
R31  12.06,45.94 90 bottom
R32  71.75,41.87 270 bottom
R33  71.75,46.7 90 bottom
R34  46.35,30.95 270 bottom
R35  50.16,30.95 270 bottom
R36  10.79,33.49 90 bottom
R37  13.33,28.41 0 bottom
R38  9.77,19.52 0 bottom
R39  10.79,16.22 90 bottom
RELAIS  38.73,19.52 0 top
RS485  59.05,44.92 90 top
RST  43.81,38.57 0 top
S1  28.57,77.94 0 top
S2  28.57,72.86 0 top
S3  28.57,67.78 0 top
S4  28.57,62.7 0 top
S5  28.57,57.62 0 top
S6  28.57,52.54 0 top
S7  28.57,47.46 0 top
S8  28.57,42.38 0 top
SWT  46.35,69.05 0 top
SWT0  74.29,77.94 0 top
SWT0_CON  64.13,77.94 0 top
SWT1  74.29,71.59 0 top
SWT1_CON  64.13,71.59 0 top
TEMP_AN  9.52,22.06 270 top
TEMP_DIG  9.52,29.68 270 top
USB  52.7,88.1 270 top
VCC  32.38,28.41 0 top
X  38.73,38.57 0 top
X1  74.29,27.14 90 top
X2  74.29,44.92 90 top
ZIGBEE  4.44,43.65 270 top

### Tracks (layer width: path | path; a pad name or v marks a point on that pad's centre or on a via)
5V
  Bottom 0.254: R27.2 6.98,24.09 11.55,24.09 13.33,25.87 15.62,25.87 18.41,28.66 20.95,28.66 21.97,29.68 21.97,32.98 22.47,33.49 26.03,33.49 27.3,32.22
  Bottom 0.61: POWER.6 POWER.4 POWER.2 76.83,17.74 75.56,19.01 53.21,19.01 | 53.21,19.01 52.95,19.01 43.3,28.66 43.3,30.7 K1.1 41.78,32.22 D1.C 34.92,32.22 5V.3 | JP1.3 63.11,40.86 62.61,40.35 53.46,40.35 53.21,40.09 53.21,19.01 | 5V.1 5V.2 5V.4 5V.3 | 5V.1 5V.3 | 27.3,24.6 27.3,32.22 28.57,33.49 5V.1 | 27.3,24.6 C10.2 | 27.3,24.6 MPX4250.P$3
A16
  Bottom 0.254: A16-A23.1 6.98,93.18 6.98,94.96 7.74,95.72 9.52,95.72 CON2.53
A17
  Top 0.254: CON2.54 10.79,93.18 9.52,91.91 A16-A23.2
A18
  Bottom 0.254: A16-A23.3 4.44,90.64 4.44,95.47 4.69,95.72 6.47,95.72 7.74,96.99 CON2.55
A19
  Bottom 0.254: CON2.56 9.52,93.18 9.52,90.64 A16-A23.4
A20
  Top 0.254: CON2.57 4.44,95.72 4.44,88.1 A16-A23.5
A21
  Top 0.254: A16-A23.6 6.98,88.1 6.98,93.18 CON2.58
A22
  Bottom 0.254: A16-A23.7 3.17,84.29 1.9,85.56 1.9,95.72 CON2.59
A23
  Top 0.254: A16-A23.8 6.98,83.02 4.44,83.02 3.17,84.29 CON2.60
AD0
  Bottom 0.254: AD0-AD7.1 30.35,91.91 32.38,93.94 32.38,95.21 32.89,95.72 34.92,95.72 CON2.33
AD1
  Bottom 0.254: AD0-AD7.2 33.65,91.91 CON2.34
AD2
  Top 0.254: CON2.35 32.38,95.72 32.38,93.94 31.11,92.67 31.11,90.64 AD0-AD7.3
AD3
  Top 0.254: AD0-AD7.4 33.65,90.64 CON2.36
AD4
  Bottom 0.254: CON2.37 29.84,95.72 29.84,93.94 27.81,91.91 27.81,88.86 AD0-AD7.5
AD5
  Top 0.254: CON2.38 29.84,93.18 29.08,93.18 27.81,91.91 27.81,89.12 28.82,88.1 31.11,88.1 AD0-AD7.6
AD6
  Top 0.254: 28.06,86.07 28.57,85.56 | 28.57,85.56 AD0-AD7.7 | CON2.39 27.3,95.72 27.3,86.83 28.57,85.56
AD7
  Bottom 0.254: CON2.40 28.57,93.43 27.3,92.16 27.3,84.29 28.57,83.02 31.11,83.02 AD0-AD7.8
AD8
  Bottom 0.254: CON2.41 27.3,95.72 27.3,93.18 24.76,90.64 19.68,90.64 AD8-AD15.1
AD9
  Bottom 0.254: AD8-AD15.2 23.49,91.91 CON2.42
AD10
  Bottom 0.254: AD8-AD15.3 17.14,90.64 17.14,92.67 17.65,93.18 21.97,93.18 22.22,93.43 22.22,95.72 CON2.43
AD11
  Top 0.254: AD8-AD15.4 22.22,89.37 23.49,90.64 CON2.44
AD12
  Bottom 0.254: CON2.49 14.6,95.72 14.6,89.37 17.14,86.83 AD8-AD15.5
AD13
  Bottom 0.254: CON2.50 15.87,89.37 17.14,88.1 19.68,88.1 AD8-AD15.6
AD14
  Bottom 0.254: CON2.51 12.06,95.72 12.06,89.37 17.14,84.29 AD8-AD15.7
AD15
  Bottom 0.254: CON2.52 13.33,89.37 17.14,85.56 19.68,85.56 AD8-AD15.8
ADC
  Bottom 0.254: C12.1 22.22,41.11 20.95,39.84 19.68,39.84 HUMIDITY.2 17.14,44.92 HSP15.2
ALE
  Bottom 0.254: EXT.1 42.54,93.18 44.57,93.18 45.08,93.69 45.08,94.96 45.84,95.72 50.16,95.72 CON2.21
AVCC
  Top 0.254: ADC.1 46.35,40.09 45.08,38.82 45.08,33.74 49.91,28.92 49.91,14.69 48.64,13.42 48.64,8.09 46.35,5.8 CON1.36
AVRH
  Top 0.254: ADC.2 48.89,40.86 48.64,40.6 47.62,40.6 45.59,38.57 45.59,34 50.41,29.17 50.41,14.44 49.14,13.17 49.14,7.84 47.62,6.31 47.62,4.28 CON1.37
AVSS
  Top 0.254: ADC.3 51.43,41.62 49.91,40.09 47.87,40.09 46.1,38.32 46.1,34.25 50.92,29.43 50.92,14.19 49.65,12.92 49.65,6.31 CON1.38
CLK
  Bottom 0.254: CON2.32 38.73,86.83 40,85.56 42.54,85.56 EXT.8
DI
  Bottom 0.254: IC1.4 66.96,52.24 64.13,55.08 60.32,55.08 59.05,53.81 RS485.3
DQ
  Bottom 0.254: TEMP_DIG.1 9.52,27.14 9.33,26.95 R1.1 6.41,26.95 6.22,27.14 6.22,27.65 4.44,29.43 DS1820.B
DVM
  Bottom 0.254: USB.2 53.97,91.91 55.24,93.18 55.24,95.21 55.75,95.72 60.32,95.72 CON2.13
DVP
  Bottom 0.254: CON2.14 61.34,94.45 56.26,89.37 52.7,89.37 USB.1
GND  (via drill 0.7)
  other vias: 75.56,63.97 61.59,65.24 71.75,67.78 47.62,47.46 64.13,81.75 75.56,81.75 23.49,81.75 31.11,81.75 46.6,82.77 14.6,81.75 9.52,50 5.71,65.24 7.49,34 27.3,19.52 32.38,18.25 47.62,19.52 45.08,22.06 28.82,36.79 12.06,11.9 12.06,39.84 14.6,55.08 46.35,65.49 57.53,92.16 40,24.6 47.62,28.41 33.65,43.65 26.54,40.35 30.35,54.83 30.6,44.67 30.35,49.75 30.6,59.91 30.35,64.99 30.35,69.81 30.6,75.15 10.28,77.94 69.21,48.73 75.56,55.08 76.83,45.17 78.1,41.11 67.94,62.7 67.94,58.89 60.32,74.13 14.6,70.32 25.52,29.68 19.68,30.95 24.76,34.76
  pour Bottom (isolate 0.305): 0.63,99.53 79.37,99.53 79.37,0.47 0.63,0.47
  pour Top (isolate 0.305): 0.63,99.53 79.37,99.53 79.37,0.47 0.63,0.47
GND_AC
  Bottom 0.254: R31.1 12.06,43.65 13.33,42.38 HUMIDITY.3
HAK
  Bottom 0.254: CON2.26 47.87,92.93 48.89,92.93 49.4,92.42 49.4,90.89 47.62,89.12 47.62,87.34 47.11,86.83 EXT.6
HCON
  Top 0.254: USB.5 50.16,86.83 50.16,91.15 50.92,91.91 52.19,91.91 53.97,93.69 CON2.20
HRQ
  Bottom 0.254: EXT.5 40,88.1 40,95.21 40.51,95.72 44.57,95.72 45.84,96.99 CON2.25
HVM
  Top 0.254: CON2.17 57.78,95.72 57.78,93.94 55.24,91.4 55.24,89.37 USB.4
HVP
  Top 0.254: USB.3 52.7,89.37 52.7,91.4 53.21,91.91 53.97,91.91 CON2.18
INT0
  Top 0.254: CON1.21 27.3,4.28 27.3,6.57 28.32,7.58 28.32,11.14 29.84,12.66 29.84,14.44 INT.1
INT1
  Top 0.254: INT.2 32.38,14.44 32.38,12.66 31.62,11.9 29.84,11.9 28.82,10.88 28.82,5.8 CON1.22
INT2  (via drill 0.7)
  Top 0.254: ZIGBEE.8 6.73,42.38 8,41.11 8,37.3 12.31,32.98 12.31,24.09 13.58,22.82 17.65,22.82 19.17,21.3 19.17,20.79 23.49,16.47 26.54,16.47 27.3,15.71 27.3,14.44 26.54,13.68 v26.03,13.68
  Bottom 0.254: v26.03,13.68 26.28,13.68 26.79,13.17 INT.3 31.87,13.17 33.14,11.9 34.41,11.9 35.17,11.14 35.17,7.07 34.92,6.82 34.92,4.79 34.41,4.28 32.38,4.28 CON1.23
INT3  (via drill 0.7)
  Top 0.254: ZIGBEE.7 4.44,41.11 6.73,41.11 7.49,40.35 7.49,37.05 11.81,32.73 11.81,23.58 13.08,22.31 17.39,22.31 18.66,21.04 18.66,20.54 24,15.2 v26.03,15.2 | CON1.24 29.84,6.82 29.84,8.6 30.6,9.36 31.62,9.36 32.38,10.12 32.38,11.39 33.65,12.66 INT.4
  Bottom 0.254: INT.4 32.38,14.44 27.05,14.44 26.28,15.2 v26.03,15.2
INT4  (via drill 0.7)
  Top 0.254: ZIGBEE.9 4.44,38.57 6.47,38.57 6.98,38.06 6.98,36.79 11.3,32.47 11.3,23.33 12.82,21.81 17.14,21.81 18.16,20.79 18.16,20.28 21.46,16.98 21.46,13.42 24.25,10.63 v26.03,10.63 | INT.5 29.33,8.85 29.33,6.57 29.84,6.06 29.84,4.79 30.35,4.28 31.62,4.28 32.89,3.01 CON1.25
  Bottom 0.254: v26.03,10.63 INT.5
INT5  (via drill 0.7)
  Top 0.254: ZIGBEE.5 4.44,43.65 6.22,43.65 8.5,41.36 8.5,37.55 12.82,33.24 12.82,24.35 13.84,23.33 17.9,23.33 19.68,21.55 19.68,21.04 23.74,16.98 27.3,16.98 28.06,16.22 28.06,13.17 27.05,12.15 v26.03,12.15 | INT.6 32.38,9.36 32.38,7.33 33.65,6.06 CON1.26
  Bottom 0.254: v26.03,12.15 26.28,11.9 31.87,11.9 33.14,10.63 INT.6
INT6  (via drill 0.7)
  Top 0.254: CON1.27 34.92,4.28 32.89,4.28 32.38,4.79 32.38,6.31 31.11,7.58 INT.7 | ZIGBEE.12 10.79,32.22 10.79,23.08 12.57,21.3 16.89,21.3 17.65,20.54 17.65,20.03 20.95,16.73 20.95,13.17 25.01,9.11 v26.03,9.11
  Bottom 0.254: v26.03,9.11 30.09,9.11 INT.7
INT7
  Top 0.254: INT.8 CON1.28
MD0
  Top 0.254: CON2.29 42.54,95.72 42.54,93.94 41.78,93.18 40.76,93.18 39.49,91.91 39.49,84.29 38.73,83.53 35.17,83.53 33.9,82.26 33.9,47.71 36.7,44.92 MD.1 37.21,44.92
MD1
  Top 0.254: CON2.28 43.81,93.69 42.54,92.42 42.54,83.53 42.03,83.02 35.43,83.02 34.41,82 34.41,47.97 35.43,46.95 39.49,46.95 40,46.44 MD.2
MD2
  Top 0.254: CON2.27 45.08,95.72 45.08,83.27 44.32,82.51 35.68,82.51 34.92,81.75 34.92,48.22 35.68,47.46 41.27,47.46 42.54,46.19 MD.3
N$1
  Bottom 0.254: SWT1_CON.1 61.59,69.81 62.61,68.8 70.23,68.8 71.75,70.32 SWT1.1
N$2
  Bottom 0.254: R18.1 DIL-SWT.16 36.19,80.48 35.68,79.97 35.68,67.78 36.19,67.27 36.95,67.27 37.46,67.78 SWT.1
N$3
  Bottom 0.254: R19.1 DIL-SWT.15 40,81.75 39.49,82.26 35.94,82.26 35.17,81.5 35.17,67.53 35.94,66.76 39.49,66.76 40,67.27 SWT.2
N$4
  Bottom 0.254: R20.1 DIL-SWT.14 40.25,82.77 35.68,82.77 34.67,81.75 34.67,67.27 35.68,66.26 41.78,66.26 42.54,67.02 SWT.3
N$5
  Bottom 0.254: R21.1 DIL-SWT.13 45.08,81.75 44.57,82.26 41.52,82.26 40.51,83.27 35.43,83.27 34.16,82 34.16,67.02 35.43,65.75 44.57,65.75 45.08,66.26 SWT.4
N$6
  Bottom 0.254: R22.1 DIL-SWT.12 47.62,81.75 49.14,83.27 57.02,83.27 58.29,82 58.29,66.76 57.02,65.49 48.38,65.49 47.62,66.26 SWT.5
N$7
  Bottom 0.254: R23.1 DIL-SWT.11 50.16,81.75 51.18,82.77 56.76,82.77 57.78,81.75 57.78,67.02 56.76,66 50.67,66 50.16,66.51 SWT.6
N$8
  Bottom 0.254: R24.1 DIL-SWT.10 52.7,81.75 53.21,82.26 56.51,82.26 57.27,81.5 57.27,67.27 56.51,66.51 53.21,66.51 52.7,67.02 SWT.7
N$9
  Bottom 0.254: R25.1 DIL-SWT.9 56.26,80.48 56.76,79.97 56.76,67.53 56.26,67.02 55.75,67.02 55.24,67.53 SWT.8
N$10
  Bottom 0.254: SWT1_CON.2 64.13,70.32 64.89,69.56 68.45,69.56 69.21,70.32 69.21,72.86 69.97,73.62 73.78,73.62 74.29,73.11 SWT1.2
N$11
  Bottom 0.254: SWT1_CON.3 66.67,72.86 67.94,74.13 75.56,74.13 76.83,72.86 SWT1.3
N$12
  Bottom 0.254: SWT0.1 71.75,76.67 70.48,75.4 62.61,75.4 61.59,76.42 SWT0_CON.1
N$13
  Bottom 0.254: SWT0_CON.2 64.13,76.67 64.89,75.91 68.45,75.91 69.21,76.67 69.21,79.21 69.97,79.97 73.78,79.97 74.29,79.46 SWT0.2
N$14
  Bottom 0.254: SWT0.3 76.83,79.21 75.56,80.48 67.69,80.48 66.67,79.46 SWT0_CON.3
N$15
  Bottom 0.254: R2.1 19.68,79.21 20.95,77.94 BUT.1 21.46,74.13 25.27,77.94 | 25.27,77.94 S1.2 | C1.2 26.22,78.89 25.27,77.94
N$16
  Bottom 0.254: 25.27,72.86 24,71.59 BUT.2 18.09,74.45 R3.1 | 25.27,72.86 S2.2 | C2.2 26.22,73.81 25.27,72.86
N$17
  Bottom 0.254: 25.27,67.78 24,69.05 BUT.3 19.68,69.05 18.09,70.64 R4.1 | 25.27,67.78 S3.2 | C3.2 26.22,68.73 25.27,67.78
N$18
  Bottom 0.254: 25.27,62.7 S4.2 | 25.27,62.7 21.46,66.51 BUT.4 19.26,66.51 18.09,67.68 R5.1 | C4.2 26.22,63.65 25.27,62.7
N$19
  Bottom 0.254: R6.1 BUT.5 21.46,63.97 24,61.43 24,58.89 25.27,57.62 | 25.27,57.62 S5.2 | C5.2 26.22,58.57 25.27,57.62
N$20
  Bottom 0.254: 25.27,52.54 S6.2 | 25.27,52.54 23.49,54.32 23.49,58.89 BUT.6 19.26,61.43 18.09,60.26 R7.1 | C6.2 26.22,53.49 25.27,52.54
N$21
  Bottom 0.254: BUT.7 20.53,58.89 | BUT.7 22.22,58.89 22.98,58.13 22.98,51.78 25.32,49.44 S7.2 25.27,47.46 26.22,48.41 C7.2 | R8.1 20.63,58.89 BUT.7
N$22
  Bottom 0.254: 25.27,42.38 24.76,42.38 23.49,43.65 23.49,50.51 20.95,53.05 | 20.95,53.05 BUT.8 | R9.1 20.44,52.54 20.95,53.05 | S8.2 25.27,42.38 | C8.2 26.22,43.33 25.27,42.38
N$23
  Bottom 0.254: LED1.A 38.73,56.1 37.12,57.71 36.29,57.71 R10.2
N$24
  Bottom 0.254: R10.1 36.19,53.05 LED.1
N$25
  Bottom 0.254: LED2.A 38.73,60.92 36.86,62.79 36.29,62.79 R11.2
N$26
  Bottom 0.254: R11.1 36.19,60.67 37.46,59.4 39.49,59.4 40,58.89 LED.2
N$27
  Bottom 0.254: LED3.A 43.81,56.1 42.2,57.71 41.37,57.71 R12.2
N$28
  Bottom 0.254: R12.1 41.27,53.05 LED.3
N$29
  Bottom 0.254: LED4.A 43.81,61.18 42.2,62.79 41.37,62.79 R13.2
N$30
  Bottom 0.254: R13.1 41.27,60.67 42.54,59.4 44.32,59.4 45.08,58.64 LED.4
N$31
  Bottom 0.254: LED5.A 48.89,56.1 47.28,57.71 46.45,57.71 R14.2
N$32
  Bottom 0.254: R14.1 46.35,53.05 LED.5
N$33
  Bottom 0.254: LED6.A 48.89,60.92 47.02,62.79 46.45,62.79 R15.2
N$34
  Bottom 0.254: R15.1 46.35,60.67 47.62,59.4 49.65,59.4 50.16,58.89 LED.6
N$35
  Bottom 0.254: LED7.A 53.97,55.84 52.1,57.71 51.53,57.71 R16.2
N$36
  Bottom 0.254: R16.1 51.43,53.05 LED.7
N$37
  Bottom 0.254: LED8.A 53.97,61.18 52.36,62.79 51.53,62.79 R17.2
N$38
  Bottom 0.254: R17.1 51.43,60.67 52.7,59.4 54.73,59.4 55.24,58.89 LED.8
N$39
  Bottom 0.254: R37.1 14.85,28.41 15.87,29.43 DCF77.1 18.22,32.03 DCF-77_CON.3
N$40
  Bottom 0.254: LM335Z.2 5.39,21.11 R27.1 6.98,19.52 R38.2
N$41
  Bottom 0.254: LDR.1 13.33,24.6 12.38,23.65 R28.2 12.57,22.06 12.85,21.78 NSL19M51.1
N$42
  Bottom 0.254: MPX4250.P$1 20.95,19.52 19.59,20.88 19.59,21.96 R29.2
N$43
  Bottom 0.254: 20.95,24.6 PRESS.1 | R29.1 21.39,24.16 20.95,24.6 | R30.1 21.39,25.04 20.95,24.6
N$44
  Bottom 0.254: BUZ.1 65.4,58.89 64.13,57.62 BUZZER.1
N$45
  Bottom 0.254: BUZ.2 75.48,58.97 73.02,61.43 61.59,61.43 BUZZER.2
N$46
  Bottom 0.254: R31.2 12.06,47.46 13.33,48.73 20.95,48.73 22.22,47.46 C12.2
N$47
  Bottom 0.254: R36.2 10.79,35.52 | 10.79,35.52 R26.1 | DCF-77_CON.2 10.8,35.51 10.79,35.52
N$48
  Bottom 0.254: R38.1 10.79,19.45 | R38.1 10.79,19.52 R39.2 | TEMP_AN.1 10.79,20.79 10.79,19.59 R38.1
N$50
  Bottom 0.254: 62.86,44.92 JP1.2 64.13,44.92 65.4,43.65 65.4,42.38 66.76,41.02 71.65,41.02 R32.2
N$51
  Bottom 0.254: R33.1 69.53,45.75 JP2.1
N$52
  Bottom 0.254: 75.56,47.46 75.56,50 74.61,50.95 IC1.7 | 75.56,47.46 X2.2 | 75.56,47.46 75.56,44.92 74.8,44.16 70.48,44.16 JP2.2
N$53
  Bottom 0.254: IC1.6 76.5,51.59 78.1,50 78.1,44.92 75.56,42.38 X2.1 75.16,42.82 R32.1
N$54
  Top 1.93: K1.P1 K1.P2 63.37,35.27 64.13,36.03 70.48,36.03 71.75,34.76 71.75,28.41 73.02,27.14 X1.2
N$55  (via drill 0.7)
  Top 0.254: RELAIS.1 37.46,20.79 37.46,25.87 41.27,29.68 41.27,33.49 v42.54,34.76
  Bottom 0.254: v42.54,34.76 43.81,34.76 46.35,32.22 R34.1
N$57
  Bottom 1.676: 75.56,22.06 75.56,22.12 X1.1
  Bottom 1.93: K1.S2 K1.S1 69.72,22.06 75.56,22.06
N$58
  Bottom 1.676: 75.56,32.22 75.58,32.2 X1.3
  Bottom 1.93: K1.O1 K1.O2 58.29,35.27 59.05,36.03 74.29,36.03 75.56,34.76 75.56,32.22
N$59
  Bottom 0.254: 50.16,30.19 R35.2 R34.2 | 50.16,30.19 50.07,30.1 | Q1.2 50.29,34.63 51.43,33.49 51.43,30.95 50.67,30.19 50.16,30.19
N$61  (via drill 0.7)
  Top 0.406: v48.89,25.87 45.59,25.87 K1.2 41.78,22.06 D1.A
  Bottom 0.406: Q1.3 52.19,35.78 52.19,27.9 50.16,25.87 v48.89,25.87
P30
  Top 0.254: ZIGBEE.3 1.9,46.19 1.9,19.52 P30-P37.1 3.17,15.71 1.9,14.44 1.9,4.28 CON1.1
P31
  Top 0.254: CON1.2 3.17,13.17 4.44,14.44 6.47,14.44 7.74,15.71 P30-P37.2
  Bottom 0.254: P30-P37.2 8.25,16.98 6.98,18.25 3.17,18.25 2.66,18.76 2.66,32.98 3.17,33.49 5.2,33.49 7.49,35.78 7.49,45.68 ZIGBEE.4
P32
  Top 0.254: P30-P37.3 4.44,11.9 4.44,4.28 CON1.3
  Bottom 0.254: ZIGBEE.6 4.44,43.65 4.44,35.01 3.93,34.51 2.66,34.51 1.65,33.49 1.65,18.25 2.66,17.23 3.68,17.23 4.44,16.47 4.44,14.44 P30-P37.3
P33
  Top 0.254: CON1.4 6.98,6.82 6.98,11.14 8.25,12.41 P30-P37.4
  Bottom 0.254: P30-P37.4 6.98,14.44 6.98,16.98 6.22,17.74 2.92,17.74 2.15,18.5 2.15,33.24 2.92,34 4.95,34 6.98,36.03 6.98,38.57 ZIGBEE.10
P34
  Top 0.254: P30-P37.5 5.71,11.14 6.98,12.41 6.98,13.68 7.74,14.44 9.01,14.44 9.52,14.95 9.52,16.22 8.76,16.98 5.2,16.98 2.41,19.77 2.41,36.54 ZIGBEE.11
  Bottom 0.254: P30-P37.5 4.44,9.36 4.44,4.79 4.95,4.28 6.47,4.28 7.74,3.01 CON1.5
P35
  Bottom 0.254: CON1.6 9.52,6.82 9.52,9.36 P30-P37.6
P36
  Bottom 0.254: P30-P37.7 6.98,6.82 6.98,5.04 7.74,4.28 9.52,4.28 CON1.7
P37
  Top 0.254: P30-P37.8 CON1.8
P40
  Bottom 0.254: CON1.9 12.06,4.28 12.06,6.06 13.84,7.84 13.84,13.42 16.12,15.71 P40-P47.1
P41
  Bottom 0.254: P40-P47.2 18.41,14.44 15.87,14.44 14.35,12.92 14.35,7.58 13.33,6.57 CON1.10
P44
  Bottom 0.254: CON1.17 22.98,3.01 21.71,4.28 17.65,4.28 17.14,4.79 17.14,6.06 15.87,7.33 15.87,9.36 P40-P47.5
P47
  Bottom 0.254: P40-P47.8 18.41,9.36 18.41,11.14 19.17,11.9 20.19,11.9 26.03,6.06 CON1.20
P70
  Top 0.254: P70-P77.1 53.21,15.71 50.16,12.66 50.16,4.28 CON1.39
P71
  Top 0.254: P70-P77.2 55.24,14.44 52.7,14.44 51.18,12.92 51.18,5.8 CON1.40
P72
  Top 0.254: CON1.41 52.7,4.28 52.7,6.57 51.68,7.58 51.68,12.15 52.7,13.17 P70-P77.3
P73
  Top 0.254: P70-P77.4 55.24,11.9 52.95,11.9 52.19,11.14 52.19,7.84 53.97,6.06 CON1.42
P74
  Bottom 0.254: P70-P77.5 55.24,9.36 55.24,4.28 CON1.43
P75
  Bottom 0.254: P70-P77.6 57.78,9.36 57.78,6.82 CON1.44
P76
  Top 0.254: P70-P77.7 55.24,6.82 55.24,4.79 55.75,4.28 57.78,4.28 CON1.45
P77
  Top 0.254: P70-P77.8 CON1.46
P80
  Top 0.254: P80-P87.1 64.13,15.71 61.59,13.17 CON1.48
P81
  Top 0.254: CON1.49 62.86,4.28 62.86,13.17 64.13,14.44 66.67,14.44 P80-P87.2
P82
  Top 0.254: CON1.50 64.13,11.9 P80-P87.3
P83
  Top 0.254: CON1.51 65.4,4.28 65.4,6.06 66.67,7.33 66.67,11.9 P80-P87.4
P84
  Bottom 0.254: CON1.52 65.4,6.82 64.64,6.82 64.13,7.33 64.13,9.36 P80-P87.5
P85
  Bottom 0.254: P80-P87.6 70.48,8.09 70.48,4.28 CON1.53
P86
  Bottom 0.254: P80-P87.7 65.91,8.09 67.94,6.06 68.7,6.06 CON1.54
P87
  Top 0.254: CON1.55 71.24,3.01 69.97,4.28 68.45,4.28 67.94,4.79 P80-P87.8
P96
  Bottom 0.254: P90-P96.7 43.3,8.09 45.08,6.31 45.08,4.28 CON1.35
PA0
  Top 0.254: PA0-PA7.1 74.29,85.56 72.51,85.56 70.48,83.53 70.48,52.03 69.97,51.52 58.29,51.52 55.24,48.48 55.24,43.9 50.41,39.08 48.38,39.08 47.11,37.81 47.11,34.76 51.94,29.93 51.94,18.76 52.95,17.74 70.99,17.74 71.75,16.98 CON1.56
PA1
  Top 0.254: CON1.57 74.29,3.77 73.02,5.04 73.02,17.49 72.26,18.25 53.21,18.25 52.45,19.01 52.45,30.19 47.62,35.01 47.62,37.55 48.64,38.57 50.67,38.57 55.75,43.65 55.75,48.22 58.54,51.02 72,51.02 72.51,51.52 72.51,65.75 73.02,66.26 PA0-PA7.2
PA2
  Top 0.254: PA0-PA7.3 77.08,86.83 77.59,86.32 77.59,81.24 75.56,79.21 75.56,67.78 73.02,65.24 73.02,51.02 72.51,50.51 58.8,50.51 56.26,47.97 56.26,43.4 52.95,40.09 52.95,19.27 53.46,18.76 76.83,18.76 78.1,17.49 78.1,7.33 77.59,6.82 75.56,6.82 CON1.58
PA3
  Top 0.254: CON1.59 75.56,1.74 73.53,1.74 73.02,2.25 73.02,3.77 72.51,4.28 70.99,4.28 70.48,4.79 70.48,16.73 69.97,17.23 52.7,17.23 51.43,18.5 51.43,29.68 46.6,34.51 46.6,38.06 48.13,39.59 50.16,39.59 54.73,44.16 54.73,48.73 58.03,52.03 69.72,52.03 69.97,52.29 69.97,84.04 72.77,86.83 PA0-PA7.4
PA4
  Top 0.254: PA0-PA7.5 76.83,89.37 78.1,88.1 78.1,51.27 76.83,50 59.05,50 56.76,47.71 56.76,43.14 53.46,39.84 53.46,19.52 53.72,19.27 77.08,19.27 78.61,17.74 78.61,7.07 77.08,5.55 CON1.60
PA5
  Bottom 0.254: CON2.1 75.56,95.72 75.56,93.94 74.29,92.67 74.29,90.64 PA0-PA7.6
PA6
  Top 0.254: PA0-PA7.7 76.83,93.18 CON2.2
PA7
  Top 0.254: CON2.3 75.56,95.72 75.56,93.94 73.53,91.91 PA0-PA7.8
PB0
  Top 0.254: P80-P86.1 71.75,91.91 71.75,92.42 72.51,93.18 73.02,93.18 CON2.4
PB1
  Top 0.254: P80-P86.2 62.86,85.56 62.86,87.34 63.62,88.1 65.4,88.1 70.48,93.18 70.48,95.72 CON2.5
PB2
  Top 0.254: P80-P86.3 65.4,86.83 71.75,93.18 CON2.6
PB3
  Top 0.254: P80-P86.4 62.86,88.1 62.86,89.88 63.62,90.64 65.4,90.64 67.94,93.18 67.94,95.72 CON2.7
PB4
  Top 0.254: P80-P86.5 65.4,89.37 69.21,93.18 CON2.8
PB5
  Top 0.254: CON2.9 65.4,95.72 65.4,93.94 64.64,93.18 63.37,93.18 62.86,92.67 62.86,91.15 61.59,89.88 P80-P86.6
PB6
  Top 0.254: P80-P86.7 65.4,91.91 66.67,93.18 CON2.10
RD  (via drill 0.7)
  Top 0.254: v48.38,91.91 50.92,94.45 CON2.22
  Bottom 0.254: EXT.2 v48.38,91.91
RDY
  Bottom 0.254: CON2.31 37.46,95.72 37.46,85.56 38.73,84.29 EXT.7
RE/_DE
  Bottom 0.254: RS485.2 59.56,44.92 61.08,46.44 61.08,53.56 62.03,54.5 63.44,54.5 66.34,51.59 66.42,51.59 | 66.42,51.59 IC1.3 | 66.42,51.59 66.42,51.52 66.99,50.95 IC1.2
RES2
  Top 0.254: CON1.31 40,4.28 40,10.63 P90-P96.3
RES3
  Top 0.254: P90-P96.6 46.35,9.36 46.35,7.33 44.57,5.55 CON1.34
RO
  Bottom 0.254: RS485.1 59.56,42.38 61.08,43.9 61.08,45.43 61.84,46.19 65.4,46.19 66.67,47.46 66.67,50 66.96,50.3 IC1.1
RST
  Top 0.254: CON2.30 38.98,92.16 38.98,84.54 38.48,84.04 34.92,84.04 33.4,82.51 33.4,46.19 36.95,42.63 42.54,42.63 43.81,41.36 RST.1
SIN0
  Bottom 0.254: CON1.11 14.6,4.28 14.6,7.07 14.85,7.33 14.85,10.88 P40-P47.3
SIN1
  Bottom 0.254: CON1.18 23.49,6.82 P40-P47.6
SIN2
  Top 0.254: P90-P96.1 41.78,15.71 38.98,12.92 38.98,7.84 37.46,6.31 37.46,4.28 CON1.29
SIN3
  Top 0.254: P90-P96.4 43.81,11.9 43.81,7.58 41.78,5.55 CON1.32
SOT0
  Bottom 0.254: CON1.12 15.36,6.06 15.36,10.63 16.63,11.9 17.9,11.9 19.17,13.17 P40-P47.4
SOT1
  Bottom 0.254: P40-P47.7 18.41,6.82 21.71,6.82 22.22,6.31 22.22,5.04 22.98,4.28 24.76,4.28 CON1.19
SOT2
  Top 0.254: P90-P96.2 43.81,14.44 41.27,14.44 39.49,12.66 39.49,6.31 CON1.30
SOT3
  Bottom 0.254: CON1.33 42.54,4.28 42.54,6.06 41.27,7.33 41.27,9.36 P90-P96.5
VBUS
  Bottom 0.254: USB.6 53.97,86.32 60.83,93.18 62.1,93.18 62.86,93.94 62.86,95.72 CON2.11
VCC  (via drill 0.7)
  Top 0.254: CON1.15 19.68,1.74 17.9,1.74 17.14,2.5 17.14,6.31 15.87,7.58 15.87,18.25 16.35,18.73 NSL19M51.2
  Top 0.406: CON2.45 22.22,95.72 24.25,95.72 24.76,95.21 24.76,85.56 | CON2.19 55.24,98.26 57.78,98.26 CON2.15 60.32,95.72 60.32,90.64 57.78,88.1 | S2.1 31.87,72.86 31.82,72.91 | S4.1 31.87,62.7 31.82,62.75 | S5.1 31.87,57.62 31.82,57.67 | S6.1 31.87,52.54 31.82,52.59 | S7.1 31.87,47.46 | v75.05,17.49 75.56,16.98 75.56,9.36
  Top 0.61: 24.76,85.56 31.82,78.5 S1.1 31.82,72.91 | 56.51,72.86 DIL-SWT.8 DIL-SWT.7 DIL-SWT.6 DIL-SWT.5 DIL-SWT.4 DIL-SWT.3 DIL-SWT.2 DIL-SWT.1 35.94,71.34 v35.94,64.73 | 56.51,72.86 57.78,74.13 57.78,88.1 | S4.1 31.82,57.67 S6.1 | 31.87,47.46 31.87,52.54 | 75.56,9.36 POWER.8 | 56.51,72.86 57.78,71.59 v57.78,53.81 58.54,53.05 v63.11,53.05 | v42.03,41.62 42.03,36.79 40,34.76 38.73,34.76 36.7,32.73 36.7,27.65 36.19,27.14 VCC.3 | S8.1 31.87,42.38 31.82,42.43 S7.1 | 31.82,62.75 31.82,67.73 31.87,67.78 | 31.87,67.78 S3.1 | 31.87,67.78 31.87,72.86 | ZIGBEE.1 3.17,51.27 4.44,52.54 20.95,52.54 22.22,51.27 22.22,38.57 23.49,37.3 v27.3,37.3 27.3,33.49 VCC.2
  Bottom 0.254: IC1.8 70.95,50.3 69.97,51.27 69.97,53.05 67.18,55.84 59.81,55.84 v57.78,53.81 | S7.1 31.87,47.46 30.92,46.51 C7.1 | S6.1 31.87,52.54 30.92,51.59 C6.1 | S5.1 31.87,57.62 30.92,56.67 C5.1 | S4.1 31.87,62.7 30.92,61.75 C4.1 | S1.1 31.87,77.94 30.92,76.99 C1.1 | S2.1 31.87,72.86 30.92,71.91 C2.1 | C3.1 30.92,66.83 31.87,67.78
  Bottom 0.406: 75.56,16.98 75.56,9.36
  Bottom 0.61: 75.56,9.36 POWER.8 | 75.56,16.98 v75.05,17.49 74.54,18 41.52,18 40.51,16.98 37.46,16.98 36.19,18.25 36.19,25.87 34.92,27.14 VCC.3 | VCC.3 VCC.4 VCC.2 VCC.1 | VCC.1 VCC.3 | VCC.1 29.33,25.36 29.33,18.25 28.32,17.23 21.2,17.23 18.92,19.52 NSL19M51.2 16.35,25.08 18.41,27.14 R30.2 | C8.1 28.57,38.57 v27.3,37.3 20.95,37.3 | 28.99,41.11 31.11,41.11 31.82,41.82 S8.1 31.82,42.18 32.38,41.62 42.54,41.62 | v42.03,41.62 42.54,41.62 | 42.54,41.62 55.75,41.62 56.51,42.38 56.51,49.24 57.78,50.51 v57.78,53.81 | S3.1 31.87,67.78 34.92,64.73 v35.94,64.73 | v63.11,53.05 JP1.1 | 20.95,37.3 C9.1 | 15.87,38.15 20.1,38.15 20.95,37.3 | 15.87,38.15 DCF-77_CON.1 15.87,35.01 12.38,31.52 12.38,31.2 | R26.2 10.89,38.15 15.87,38.15 | C11.2 R1.2 | C11.2 6.15,30.51 DS1820.E | C11.2 7.81,30.51 8.5,31.2 12.38,31.2 | 12.38,31.2 R37.2
VCC_AC
  Bottom 0.254: HUMIDITY.1 HSP15.1
WRH  (via drill 0.7)
  Top 0.254: v46.35,88.1 46.35,91.91 CON2.24
  Bottom 0.254: EXT.4 45.08,89.37 v46.35,88.1
WRL  (via drill 0.7)
  Top 0.254: v47.37,90.64 48.89,90.64 51.43,93.18 52.19,93.18 52.7,93.69 52.7,94.96 51.94,95.72 50.16,95.72 CON2.23
  Bottom 0.254: EXT.3 42.54,90.64 v47.37,90.64
X0
  Top 0.254: X.1 36.19,38.57 24.76,38.57 23.24,40.09 23.24,76.92 20.95,79.21 16.89,79.21 15.87,80.23 15.87,92.67 17.65,94.45 CON2.48
X0A
  Top 0.254: X.3 37.97,35.27 36.95,35.27 35.94,34.25 35.94,29.93 34.41,28.41 32.89,28.41 32.38,27.9 32.38,25.87 31.62,25.11 30.35,25.11 29.84,24.6 29.84,15.2 29.33,14.69 29.33,12.92 27.81,11.39 27.81,7.84 26.79,6.82 20.44,6.82 19.68,6.06 19.68,4.28 CON1.13
X1
  Top 0.254: CON2.47 19.68,95.72 19.68,93.94 18.92,93.18 17.14,93.18 16.38,92.42 16.38,80.48 17.14,79.72 21.2,79.72 23.74,77.18 23.74,40.35 25.01,39.08 36.7,39.08 X.2
X1A
  Top 0.254: X.4 38.73,38.57 38.73,36.79 37.71,35.78 36.7,35.78 35.43,34.51 35.43,33.49 32.38,30.44 32.38,29.17 31.62,28.41 30.09,28.41 29.33,27.65 29.33,15.46 28.82,14.95 28.82,13.17 27.3,11.65 27.3,8.85 26.54,8.09 25.27,8.09 24,9.36 18.92,9.36 18.41,8.85 CON1.14

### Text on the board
Top: Top
Bottom: Bot.
tPlace: PB6 | PA7 | PA6 | P20 | P21 | P10 | P11 | P00 | P01 | P50 | P51 | DVP | DVM | PB5 | PB4 | PA5 | PA4 | P22 | P23 | P12 | P13 | P02 | P03 | P52 | P53 | HVP | PB3 | PB2 | PA3 | PA2 | P24 | P25 | P14 | P15 | P04 | P05 | P54 | P55 | HVM | PB1 | PB0 | PA1 | PA0 | P26 | P27 | P16 | P17 | P06 | P07 | P56 | P57 | HCON | VBUS | 1 | 2 | V1.2 - 09/2008 | 3 | 4 | 1 | 2 | 3 | 4 | 5 | 6 | 7 | 8 | 5 | KNXcalibur - SAC | 6 | 7 | 8 | Fritz Praus | 1 | 2 | 3 | 4 | 5 | 6 | 7 | 8 | MD0 | MD1 | MD2 | DI | VCC | RE/ | DE | 510 | X1 | X1A | RO | 5V | GND | 0V | ADC | AC | AVCC | AVRH | AVSS | RST | X0 | X0A | P30 | P31 | P40 | P41 | P60 | P61 | P90 | P91 | P70 | P71 | P80 | P81 | P32 | P33 | P42 | P43 | P62 | P63 | P92 | P93 | P72 | P73 | P82 | P83 | P34 | P35 | P44 | P45 | P64 | P65 | P94 | P95 | P74 | P75 | P84 | P85 | P36 | P37 | P46 | P47 | P66 | P67 | P96 | P76 | P77 | P86 | P87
